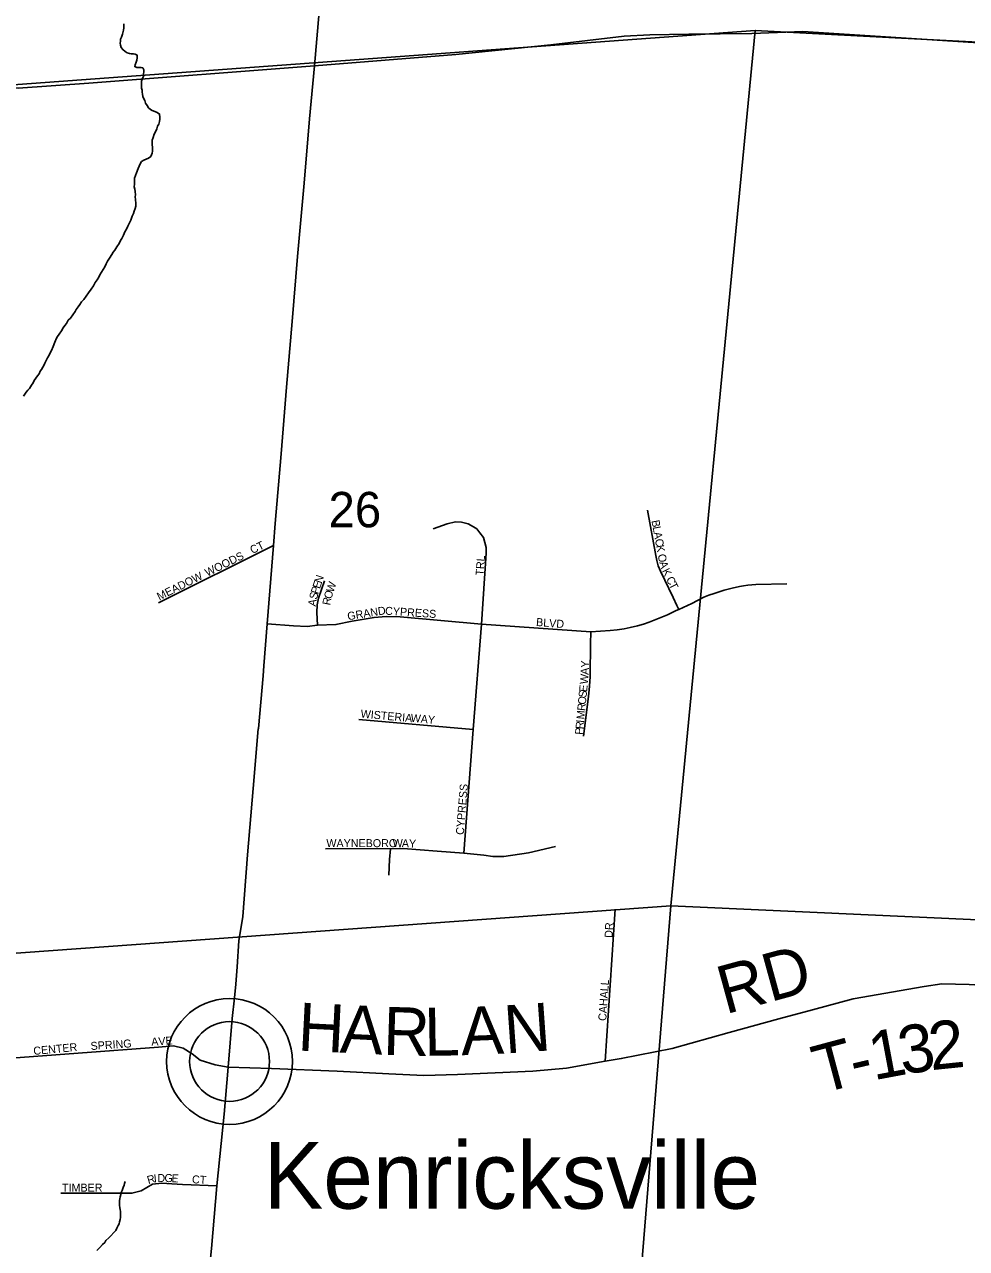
# Model space of a CAD drawing. Extents: x 0 to 1064, y 0 to 440.
# Drawn here: x 277.09 to 294.9, y 363.4 to 386.56 of the extents above; entities that cross this region are included whole.
import ezdxf

# ---------------------------------------------------------------- set-up
doc = ezdxf.new("R2010")
doc.units = 0
for name, color, linetype in [('GM_X_County_Road', 7, 'Continuous'), ('GM_X_Minor_River', 7, 'Continuous'), ('GM_X_Section', 7, 'Continuous'), ('GM_X_Section_Text', 7, 'Continuous'), ('GM_X_State_Route', 7, 'Continuous'), ('GM_X_Township_Road', 7, 'Continuous'), ('GM_X_Township_Road_Text', 7, 'Continuous'), ('GM_X_Township_Subdivision', 7, 'Continuous'), ('GM_X_Township_Subdivision_Text', 7, 'Continuous'), ('GM_X_Unincorporated', 7, 'Continuous'), ('GM_X_Unincorporated_Location', 7, 'Continuous'), ('GM_X_Unincorporated_Text', 7, 'Continuous')]:
    doc.layers.add(name, color=color, linetype=linetype)

msp = doc.modelspace()

# ---------------------------------------------------------------- linework, layer by layer
at = {"layer": 'GM_X_County_Road'}
for points in [[(282.57, 385.777), (282.57, 385.777), (278.303, 385.451), (276.969, 385.357), (275.937, 385.43), (275.355, 385.393), (274.825, 385.378), (274.183, 385.37), (272.586, 385.535), (270.899, 385.669), (269.966, 385.781), (267.503, 386.042), (266.481, 386.117), (262.54, 386.512), (259.878, 386.759), (259.413, 386.796), (258.48, 386.915), (257.845, 386.976), (257.301, 387.132), (255.591, 387.729), (252.957, 388.576), (250.745, 389.193)], [(307.393, 385.615), (307.089, 385.647), (301.588, 385.827), (298.554, 385.995), (291.807, 386.426), (291.326, 386.408), (290.846, 386.389), (289.654, 386.377), (288.913, 386.365), (288.426, 386.341), (287.042, 386.175), (285.245, 385.995), (282.57, 385.777)]]:
    msp.add_lwpolyline(points, dxfattribs=at)
at = {"layer": 'GM_X_Minor_River'}
for points in [[(278.968, 386.571), (278.966, 386.498), (278.958, 386.45), (278.938, 386.377), (278.919, 386.323), (278.905, 386.281), (278.905, 386.244), (278.898, 386.208), (278.903, 386.171), (278.914, 386.122), (278.943, 386.085), (278.991, 386.048), (279.027, 386.022), (279.069, 386.009), (279.105, 386.002), (279.142, 386.007), (279.178, 386), (279.214, 385.981), (279.219, 385.926), (279.212, 385.884), (279.198, 385.848), (279.179, 385.799), (279.172, 385.763), (279.208, 385.744), (279.244, 385.743), (279.287, 385.748), (279.323, 385.741), (279.341, 385.704), (279.346, 385.667), (279.339, 385.625), (279.338, 385.582), (279.312, 385.522), (279.299, 385.486), (279.297, 385.437), (279.296, 385.389), (279.301, 385.352), (279.313, 385.315), (279.312, 385.279), (279.317, 385.242), (279.322, 385.199), (279.339, 385.163), (279.362, 385.119), (279.373, 385.07), (279.409, 385.027), (279.432, 384.984), (279.467, 384.952), (279.503, 384.933), (279.552, 384.914), (279.594, 384.894), (279.642, 384.863), (279.646, 384.808), (279.645, 384.765), (279.638, 384.723), (279.625, 384.675), (279.599, 384.633), (279.586, 384.584), (279.566, 384.53), (279.541, 384.482), (279.521, 384.422), (279.501, 384.373), (279.5, 384.331), (279.499, 384.282), (279.504, 384.239), (279.509, 384.197), (279.508, 384.16), (279.501, 384.124), (279.475, 384.064), (279.432, 384.028), (279.389, 384.011), (279.346, 383.994), (279.302, 383.965), (279.271, 383.923), (279.258, 383.881), (279.238, 383.832), (279.206, 383.754), (279.186, 383.7), (279.167, 383.652), (279.165, 383.591), (279.164, 383.536), (279.163, 383.487), (279.174, 383.445), (279.179, 383.402), (279.183, 383.335), (279.182, 383.298), (279.187, 383.249), (279.191, 383.17)], [(279.191, 383.17), (279.19, 383.122), (279.177, 383.079), (279.163, 383.025), (279.15, 382.983), (279.124, 382.935), (279.098, 382.856), (279.059, 382.778), (279.04, 382.742), (279.015, 382.688), (278.983, 382.634), (278.957, 382.574), (278.925, 382.507), (278.9, 382.472), (278.874, 382.417), (278.83, 382.352), (278.792, 382.292), (278.76, 382.25), (278.735, 382.208), (278.696, 382.136), (278.659, 382.082), (278.633, 382.028), (278.607, 381.974), (278.575, 381.92), (278.544, 381.872), (278.512, 381.824), (278.493, 381.776), (278.461, 381.728), (278.423, 381.674), (278.391, 381.614), (278.347, 381.548), (278.297, 381.483), (278.253, 381.417), (278.208, 381.357), (278.165, 381.309), (278.133, 381.262), (278.101, 381.214), (278.064, 381.166), (278.045, 381.13), (278, 381.064), (277.956, 381.004), (277.913, 380.963), (277.881, 380.903), (277.849, 380.861), (277.818, 380.819), (277.786, 380.765), (277.742, 380.699), (277.71, 380.658), (277.691, 380.621), (277.659, 380.549), (277.626, 380.465), (277.594, 380.393), (277.569, 380.345), (277.555, 380.302), (277.524, 380.254), (277.498, 380.2), (277.472, 380.152), (277.459, 380.116), (277.434, 380.074), (277.409, 380.032), (277.383, 379.996), (277.364, 379.948), (277.333, 379.912), (277.301, 379.864), (277.269, 379.823), (277.25, 379.781), (277.219, 379.733), (277.181, 379.673), (277.149, 379.637), (277.118, 379.601), (277.093, 379.565), (277.067, 379.523)], [(278.455, 363.357), (278.511, 363.417), (278.561, 363.47), (278.605, 363.506), (278.624, 363.548), (278.68, 363.595), (278.717, 363.637), (278.774, 363.696), (278.811, 363.738), (278.83, 363.78), (278.856, 363.828), (278.875, 363.864), (278.882, 363.9), (278.895, 363.942), (278.902, 363.979), (278.903, 364.015), (278.904, 364.058), (278.899, 364.094), (278.894, 364.131), (278.889, 364.168), (278.884, 364.216), (278.885, 364.259), (278.886, 364.301), (278.887, 364.338), (278.894, 364.374), (278.908, 364.417), (278.915, 364.453), (278.934, 364.495), (278.953, 364.549), (278.973, 364.591), (278.98, 364.628), (278.993, 364.664)]]:
    msp.add_lwpolyline(points, dxfattribs=at)
at = {"layer": 'GM_X_Section'}
for points in [[(274.457, 385.242), (290.907, 386.449), (289.312, 369.882), (273.003, 368.703)], [(290.907, 386.449), (307.65, 385.572), (306.185, 369.112), (289.312, 369.882)], [(273.003, 368.703), (289.312, 369.882), (287.989, 353.559), (271.58, 351.945)], [(289.312, 369.882), (306.185, 369.112), (304.793, 352.705), (287.989, 353.559)]]:
    msp.add_lwpolyline(points, close=True, dxfattribs=at)
at = {"layer": 'GM_X_State_Route'}
for points in [[(281.615, 374.424), (281.677, 375.216), (281.793, 376.699), (281.825, 377.114), (281.943, 378.437), (282.042, 379.694), (282.147, 380.939), (282.252, 382.171), (282.378, 383.555), (282.476, 384.776), (282.57, 385.777), (282.705, 387.319), (282.865, 389.134), (282.903, 390.425), (283.152, 393.255), (283.24, 394.027), (283.348, 395.417), (283.43, 396.412), (283.477, 396.916), (283.541, 397.519), (283.648, 398.432), (283.726, 399.251), (283.757, 399.603), (283.774, 400.28)], [(280.587, 363.026), (280.621, 363.398), (280.725, 364.581), (280.86, 365.938), (280.94, 366.828), (281.014, 367.746), (281.057, 368.142), (281.084, 368.4), (281.106, 368.726), (281.14, 369.22), (281.214, 369.676), (281.305, 370.848), (281.41, 372.099), (281.507, 373.228), (281.513, 373.234), (281.601, 374.236), (281.615, 374.424)]]:
    msp.add_lwpolyline(points, dxfattribs=at)
at = {"layer": 'GM_X_Township_Road'}
msp.add_lwpolyline([(280.94, 366.828), (281.76, 366.8), (283, 366.751), (283.977, 366.699), (284.637, 366.668), (285.276, 366.687), (286.703, 366.751), (287.339, 366.81), (288.069, 366.94), (288.374, 366.991), (289.338, 367.181), (290.413, 367.482), (291.352, 367.74), (291.988, 367.915), (292.758, 368.121), (294.106, 368.354), (294.438, 368.403), (294.954, 368.391), (296.652, 368.293), (301.66, 367.998), (306.061, 367.851)], dxfattribs=at)
at = {"layer": 'GM_X_Township_Subdivision'}
for points in [[(289.463, 375.491), (289.426, 375.566), (289.353, 375.716), (289.114, 376.215), (289.094, 376.259), (289.073, 376.318), (289.059, 376.363), (289.046, 376.416), (289.026, 376.511), (288.869, 377.366)], [(285.394, 370.874), (285.575, 373.218), (285.729, 375.212), (285.819, 376.555), (285.819, 376.665), (285.793, 376.759), (285.768, 376.852), (285.7, 376.937), (285.641, 377.013), (285.581, 377.056), (285.479, 377.107), (285.352, 377.141), (285.241, 377.149), (285.08, 377.107), (284.817, 377.013)], [(279.623, 375.613), (281.793, 376.699)], [(281.677, 375.216), (282.176, 375.177), (282.432, 375.167), (282.628, 375.192), (282.977, 375.202), (283.282, 375.266), (283.699, 375.339), (283.925, 375.359), (284.191, 375.349), (285.729, 375.212), (287.795, 375.063), (287.984, 375.076), (288.164, 375.089), (288.296, 375.104), (288.428, 375.125), (288.545, 375.149), (288.681, 375.182), (288.792, 375.214), (288.901, 375.251), (289.06, 375.309), (289.251, 375.389), (289.414, 375.467), (289.463, 375.491), (289.708, 375.601), (289.938, 375.72), (290.033, 375.758), (290.129, 375.794), (290.225, 375.826), (290.323, 375.855), (290.472, 375.895), (290.612, 375.924), (290.688, 375.937), (290.765, 375.948), (290.842, 375.957), (290.919, 375.964), (291.508, 375.973)], [(282.628, 375.192), (282.614, 375.433), (282.623, 375.575), (282.648, 375.703), (282.761, 376.032)], [(287.657, 373.09), (287.754, 373.845), (287.775, 374.035), (287.785, 374.218), (287.793, 374.866), (287.795, 375.041), (287.795, 375.063)], [(283.407, 373.405), (285.575, 373.218)], [(282.779, 370.959), (283.755, 370.967), (284.01, 370.959), (284.248, 370.967), (284.893, 370.917), (285.394, 370.874), (285.649, 370.849), (285.776, 370.84), (285.946, 370.815), (286.15, 370.815), (286.617, 370.883), (287.127, 371.001)], [(283.976, 370.458), (283.993, 370.755), (284.01, 370.959)], [(288.069, 366.94), (288.257, 369.816)], [(280.94, 366.828), (280.691, 366.874), (280.406, 366.96), (280.255, 367.08), (280.09, 367.187), (279.902, 367.23), (279.622, 367.208), (276.573, 366.979), (274.084, 366.824)], [(277.774, 364.445), (279.119, 364.442), (279.291, 364.488), (279.509, 364.614), (279.681, 364.63), (279.875, 364.62), (280.077, 364.607), (280.725, 364.581)]]:
    msp.add_lwpolyline(points, dxfattribs=at)
at = {"layer": 'GM_X_Unincorporated'}
for radius in [1.19, 0.755]:
    msp.add_circle((280.965, 366.935), radius, dxfattribs=at)
at = {"layer": 'GM_X_Unincorporated_Location'}
msp.add_line((280.965, 366.935), (280.965, 366.935), dxfattribs=at)

# ---------------------------------------------------------------- texts
at = {"layer": 'GM_X_Section_Text'}
msp.add_text('26', height=0.6697, rotation=0, dxfattribs=at).set_placement((282.836, 377.044))
at = {"layer": 'GM_X_Township_Road_Text'}
for s, height, rotation, p in [('RD', 0.9091, 15.3413, (290.342, 367.824)), ('H', 0.909, 357.1574, (282.242, 367.143)), ('A', 0.909, 357.1646, (283.042, 367.104)), ('R', 0.909, 358.2668, (283.86, 367.063)), ('L', 0.909, 0.9014, (284.652, 367.04)), ('A', 0.909, 2.2488, (285.355, 367.052)), ('N', 0.909, 4.0131, (286.185, 367.085)), ('3', 0.909, 9.3357, (293.691, 366.679)), ('2', 0.909, 5.8488, (294.229, 366.768)), ('1', 0.909, 10.6139, (293.146, 366.577)), ('T', 0.909, 14.9728, (292.143, 366.32)), ('-', 0.909, 13.135, (292.793, 366.494))]:
    msp.add_text(s, height=height, rotation=rotation, dxfattribs=at).set_placement(p)
at = {"layer": 'GM_X_Township_Subdivision_Text'}
for s, height, rotation, p in [('B', 0.152, 280.4287, (288.944, 377.168)), ('L', 0.152, 280.4148, (288.966, 377.05)), ('A', 0.152, 280.4186, (288.985, 376.945)), ('CT', 0.1515, 26.5487, (281.397, 376.535)), ('C', 0.152, 280.4223, (289.009, 376.814)), ('K', 0.152, 280.4183, (289.031, 376.696)), ('WOODS', 0.1515, 26.1471, (280.544, 376.108)), ('TRL', 0.1515, 85.6026, (285.768, 376.125)), ('O', 0.152, 280.432, (289.062, 376.525)), ('MEADOW', 0.1515, 26.5635, (279.637, 375.655)), ('A', 0.152, 285.9421, (289.09, 376.379)), ('K', 0.152, 296.7619, (289.138, 376.221)), ('E', 0.152, 71.5737, (282.673, 375.87)), ('N', 0.152, 71.5581, (282.707, 375.972)), ('W', 0.152, 71.0654, (282.927, 375.8)), ('C', 0.152, 296.5768, (289.216, 376.067)), ('T', 0.152, 296.5895, (289.27, 375.959)), ('S', 0.152, 76.0697, (282.615, 375.668)), ('P', 0.152, 71.9192, (282.64, 375.769)), ('O', 0.152, 72.8989, (282.888, 375.674)), ('A', 0.152, 80.8683, (282.595, 375.54)), ('R', 0.152, 78.9329, (282.866, 375.56)), ('GRAND', 0.1515, 9.2712, (283.205, 375.284)), ('CYPRESS', 0.1515, 356.1917, (283.903, 375.391)), ('BLVD', 0.1515, 355.4887, (286.758, 375.178)), ('A', 0.152, 87.4258, (287.755, 374.249)), ('Y', 0.152, 87.7298, (287.761, 374.383)), ('W', 0.152, 85.13, (287.74, 374.07)), ('S', 0.152, 84.5014, (287.715, 373.816)), ('E', 0.152, 84.5167, (287.726, 373.922)), ('R', 0.152, 84.5021, (287.691, 373.564)), ('O', 0.152, 84.5189, (287.703, 373.683)), ('WISTERIA', 0.1515, 354.8086, (283.439, 373.444)), ('WAY', 0.1515, 354.7948, (284.385, 373.364)), ('M', 0.152, 84.5105, (287.676, 373.404)), ('P', 0.152, 84.5014, (287.648, 373.112)), ('R', 0.152, 84.531, (287.658, 373.218)), ('I', 0.152, 84.5244, (287.669, 373.338)), ('CYPRESS', 0.1515, 85.2351, (285.394, 371.218)), ('WAYNEBORO', 0.1515, 0, (282.796, 370.991)), ('W', 0.152, 359.7646, (284.049, 370.991)), ('A', 0.152, 357.9016, (284.221, 370.991)), ('Y', 0.152, 357.0263, (284.354, 370.986)), ('DR', 0.1515, 86.9884, (288.208, 369.271)), ('CAHALL', 0.1515, 85.9166, (288.088, 367.698)), ('AVE', 0.1515, 3.9581, (279.488, 367.231)), ('CENTER', 0.1515, 5.2955, (277.26, 367.058)), ('SPRING', 0.1515, 3.8763, (278.341, 367.151)), ('TIMBER', 0.1515, 0, (277.796, 364.471)), ('R', 0.152, 16.5992, (279.43, 364.612)), ('I', 0.152, 5.8672, (279.538, 364.645)), ('D', 0.152, 1.224, (279.601, 364.652)), ('G', 0.152, 358.1637, (279.732, 364.655)), ('E', 0.152, 357.7039, (279.865, 364.65)), ('CT', 0.1515, 356.8222, (280.251, 364.631))]:
    msp.add_text(s, height=height, rotation=rotation, dxfattribs=at).set_placement(p)
at = {"layer": 'GM_X_Unincorporated_Text'}
msp.add_text('Kenricksville', height=1.26364, rotation=0, dxfattribs=at).set_placement((281.61, 364.149))

doc.saveas('drawing.dxf')
